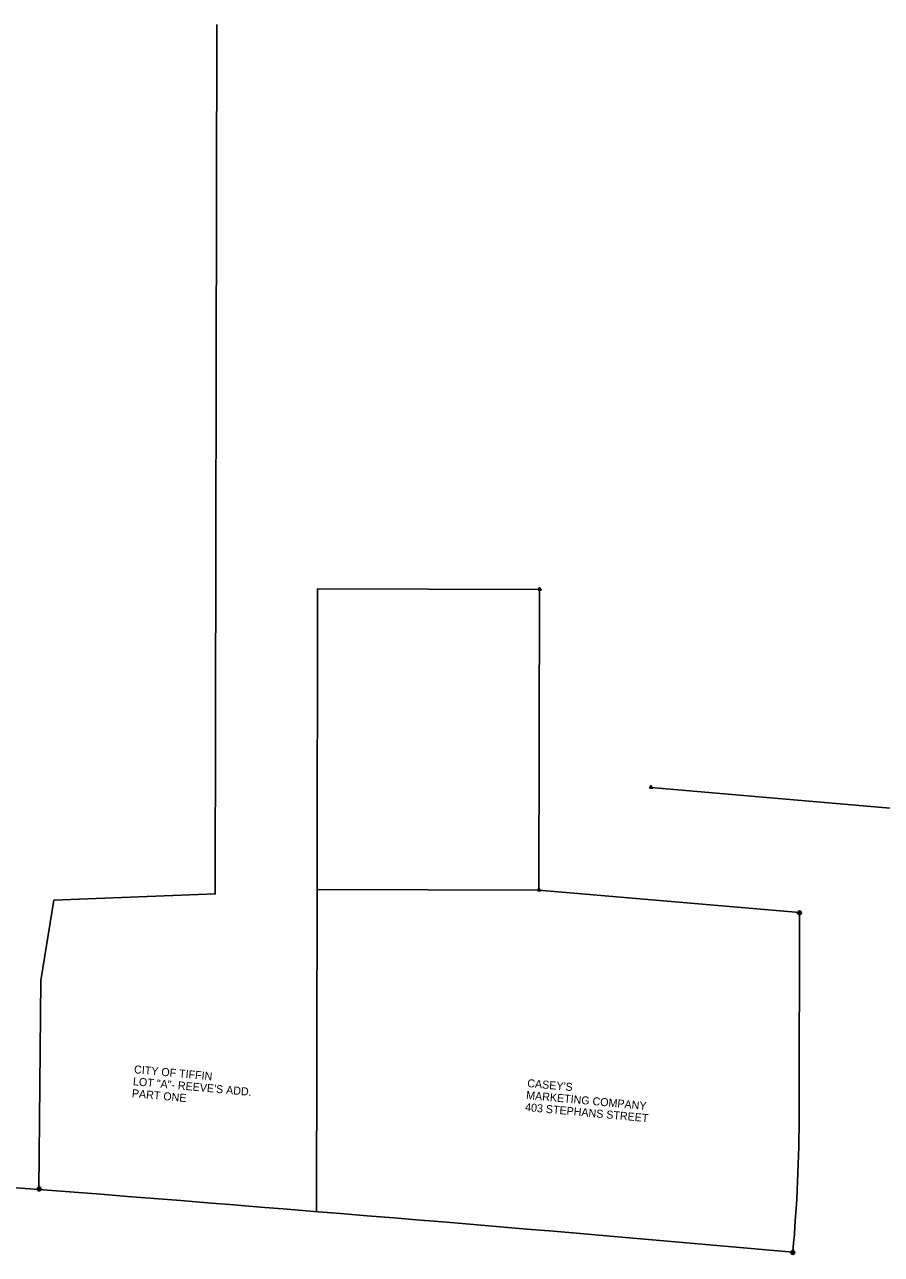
# Model space of a CAD drawing. Extents: x 20500076 to 20505422, y 7951999 to 7957351.
# Drawn here: x 20501277 to 20501783, y 7953972 to 7954698 of the extents above; entities that cross this region are included whole.
import ezdxf

# ---------------------------------------------------------------- set-up
doc = ezdxf.new("R2010")
doc.units = 0
for name, color, linetype in [('DisROW Existing', 7, 'Continuous'), ('DisROW Property Lines', 7, 'Continuous'), ('rowdsnSymbolsProposed', 7, 'Continuous'), ('SurControl', 7, 'Continuous'), ('SurSectionCorner', 7, 'Continuous'), ('Text', 7, 'Continuous')]:
    doc.layers.add(name, color=color, linetype=linetype)

msp = doc.modelspace()

# ---------------------------------------------------------------- linework, layer by layer
at = {"layer": 'DisROW Existing'}
for p, q in [((20502125.45, 7954206.14), (20501646.66, 7954247.4)), ((20501734.14, 7954056.11), (20501734.36, 7954173.59))]:
    msp.add_line(p, q, dxfattribs=at)
msp.add_lwpolyline([(20501734.36, 7954173.59), (20501580.54, 7954186.85), (20501580.89, 7954364.33)], dxfattribs=at)
for centre, radius, start, end in [((20500767.14, 7954057.98), 967, 354.96779, 359.88926), ((20498089.14, 7912778.84), 41354.94, 84.948602, 85.647544)]:
    msp.add_arc(centre, radius, start, end, dxfattribs=at)
at = {"layer": 'DisROW Property Lines'}
for points in [[(20501285.45, 7954010.07), (20501286.54, 7954133.46), (20501294.3, 7954180.83), (20501389.52, 7954184.56), (20501390.46, 7954697.69)], [(20501449.54, 7954187.1), (20501449.89, 7954364.58), (20501580.89, 7954364.33)], [(20501449.18, 7953997.05), (20501449.54, 7954187.1), (20501580.54, 7954186.85)]]:
    msp.add_lwpolyline(points, dxfattribs=at)
at = {"layer": 'rowdsnSymbolsProposed'}
for points in [[(20501580.89, 7954364.33), (20501580.89, 7954364.33)], [(20501646.66, 7954247.4), (20501646.66, 7954247.4)], [(20501580.54, 7954186.85), (20501580.55, 7954186.85)], [(20501734.36, 7954173.59), (20501734.37, 7954173.59)], [(20501285.45, 7954010.07), (20501285.45, 7954010.07)], [(20501449.18, 7953997.05), (20501449.18, 7953997.05)], [(20501730.41, 7953973.16), (20501730.41, 7953973.16)]]:
    msp.add_lwpolyline(points, dxfattribs=at)
at = {"layer": 'SurControl'}
for centre in [(20501734.34, 7954173.29), (20501285.58, 7954010.41), (20501730.37, 7953972.88)]:
    msp.add_circle(centre, 1.12, dxfattribs=at)
at = {"layer": 'SurSectionCorner'}
for points in [[(20501579.97, 7954363.8), (20501581.8, 7954363.8), (20501580.89, 7954365.38)], [(20501645.75, 7954246.87), (20501647.58, 7954246.87), (20501646.66, 7954248.45)], [(20501579.63, 7954186.32), (20501581.46, 7954186.32), (20501580.54, 7954187.9)], [(20501733.45, 7954173.06), (20501735.28, 7954173.06), (20501734.36, 7954174.65)], [(20501284.53, 7954009.54), (20501286.36, 7954009.54), (20501285.45, 7954011.13)], [(20501729.5, 7953972.63), (20501731.33, 7953972.63), (20501730.41, 7953974.22)]]:
    msp.add_lwpolyline(points, close=True, dxfattribs=at)

# ---------------------------------------------------------------- texts
at = {"layer": 'Text'}
for s, height, p in [('CITY OF TIFFIN', 4.7244, (20501341.39, 7954078.72)), ('LOT "A"- REEVE\'S ADD.', 4.7244, (20501340.75, 7954071.66)), ("CASEY'S", 4.724, (20501573.48, 7954070.58)), ('PART ONE', 4.724, (20501340.1, 7954064.61)), ('MARKETING COMPANY', 4.7244, (20501572.83, 7954063.53)), ('403 STEPHANS STREET', 4.7244, (20501572.19, 7954056.47))]:
    msp.add_text(s, height=height, rotation=354.76449, dxfattribs=at).set_placement(p)

doc.saveas('drawing.dxf')
